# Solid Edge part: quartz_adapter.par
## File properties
Title: Convex Quartz Adapter
Author: Lee Sichello
Template: Metric Part.par
Last saved by: Lee
Revision: 11
Application: Solid Edge
Material: Quartz Glass
Face Style: Model Default
Coef. of Thermal Exp: 0.0
Thermal Conductivity: 0.0
Specific Heat: 0.0
Modulus of Elasticity: 0.0
Poisson's Ratio: 0.0
Yield Stress: 0.0
Ultimate Stress: 0.0
Elongation: 0.0
Manager: Garth Huber
Company: U of R Physics
Accuracy: 0.990
Document Number: 3
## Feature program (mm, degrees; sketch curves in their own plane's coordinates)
sketch for "unnamed Protrusion 1" plane through (0, 0, 0) normal (0, 0, 1) x-axis (1, 0, 0)
  circle centre (0, 0) radius 66.5
extrude "unnamed Protrusion 1" add finite 23.464 along +normal
sketch for "unnamed RevolvedCutout 1" plane through (0, 0, 0) normal (0, -1, 0) x-axis (1, 0, 0)
  line (0, 23.464) -> (66.5, 23.464)
  line (66.5, 23.464) -> (66.5, 20)
  line (66.5, 20) -> (63.8391, 20)
  arc centre (0, 135.536) radius 132 from (0, 3.536) to (63.8391, 20) ccw
revolve "unnamed RevolvedCutout 1" cut full turn 360 deg
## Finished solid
Body 1: solid body, 4 faces, 3 edges, 0 vertices.
  Faces by surface: plane 2, cylinder 1, sphere 1
  Edges by curve: circle 3
Bounding box of the edges (mm; curved faces can reach further): 133.000 x 133.000 x 20.000, from (-66.5, -66.5, 0) to (66.5, 66.5, 20).
Cylindrical faces by radius (mm): R66.5 x1
Spherical faces by radius (mm): R132 x1
Planar faces by outward normal: +z 1, -z 1
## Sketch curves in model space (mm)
line (0, 0, 0) -> (0, 0, 135.536)
arc centre (0, 0, 135.536) radius 132 from (0, 0, 3.536) through (32.964, 0, 7.7183) to (63.8391, 0, 20)
line (66.5, 0, 20) -> (63.8391, 0, 20)
line (66.5, 0, 23.464) -> (66.5, 0, 20)
line (0, 0, 23.464) -> (66.5, 0, 23.464)
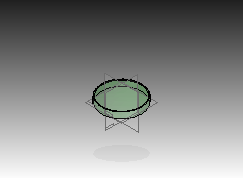
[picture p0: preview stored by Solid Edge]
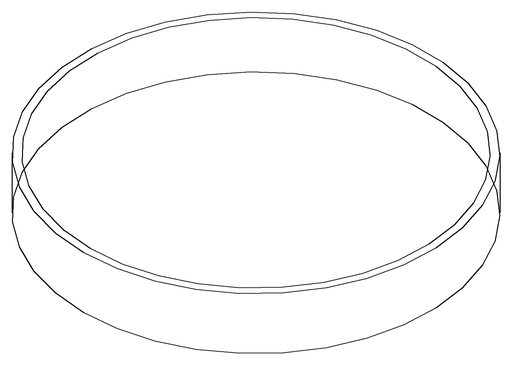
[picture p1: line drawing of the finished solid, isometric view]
